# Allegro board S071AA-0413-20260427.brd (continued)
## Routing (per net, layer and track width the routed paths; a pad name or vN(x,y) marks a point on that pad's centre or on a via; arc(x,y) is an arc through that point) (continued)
N23050554: length 1.5
  TOP w0.305: LD46.1 R46.1
N23057413: length 133.1
  L11_DPS w0.203: v1(163.86,212.67) 170.21,212.67 171.89,214.34 171.89,239.49 169.98,241.4 151.11,241.4 112.36,280.15 112.36,292.73 113.16,293.53 117.26,293.53 v1(118.38,292.42) v1(120.92,292.42)
  BOTTOM w0.152: v1(163.86,212.67) 162.9,212.67 SH5.2
N23057441: length 127.8
  L11_DPS w0.203: v1(113.3,292.42) v1(115.84,292.42) 114.39,290.97 114.39,279.37 151.87,241.88 170.86,241.88 172.64,240.11 172.64,213.5 170.81,211.68 v1(163.86,211.68)
  BOTTOM w0.152: SH6.2 v1(163.86,211.68)
N23058541: length 225.3
  L11_DPS w0.203: v1(143.78,292.42) v1(141.24,292.42) 140.31,293.35 135.28,293.35 134.48,292.55 134.48,292 135.13,291.34 137.89,291.34 141.59,287.64 141.59,272.25 155.57,258.27 197.79,258.27 205.81,250.26 205.81,223.84 206.53,223.11 206.53,200.69 194.08,188.24 159.13,188.24 150.26,197.11 v1(149.14,197.11)
  BOTTOM w0.152: SH7.2 v1(149.14,197.11)
N23058569: length 217.7
  L11_DPS w0.203: v1(148.13,197.11) 157.94,187.3 194.57,187.3 207.5,200.22 207.5,223.52 206.73,224.3 206.73,250.33 198.16,258.9 156.02,258.9 142.74,272.18 142.74,288.38 v1(138.7,292.42) v1(136.16,292.42)
  BOTTOM w0.152: v1(148.13,197.11) 148.13,198.11 SH8.2
N23059275: length 153.6
  L09_DPS w0.203: v1(129.59,212.67) 129.06,212.67 120.13,221.59 120.13,242.14 113.46,248.81 79.07,248.81 66.08,261.81 66.08,290.94 63.96,293.05 42.81,293.05 v1(42.18,292.42) v1(39.64,292.42)
  BOTTOM w0.152: SH9.2 v1(129.59,212.67)
N23059303: length 158.8
  L09_DPS w0.203: v1(34.56,292.42) v1(37.1,292.42) 38.34,293.66 64.65,293.66 67.13,291.17 67.13,261.91 79.24,249.8 113.68,249.8 120.89,242.59 120.89,222.22 v1(129.59,213.51)
  BOTTOM w0.152: SH10.2 v1(129.59,213.51)
N23060072: length 110.1
  L11_DPS w0.203: v1(92.98,292.42) v1(90.44,292.42) 89.49,293.37 84.84,293.37 84.26,292.79 84.26,291.64 87.19,288.71 87.19,266.14 93.91,259.42 108.05,259.42 133.75,233.73 144.62,233.73 v1(145.14,234.25)
  BOTTOM w0.152: SH11.2 v1(145.14,234.25)
N23060100: length 99.5
  L11_DPS w0.203: v1(85.36,292.42) v1(87.9,292.42) 88.96,291.36 88.96,268.95 96.78,261.14 107.96,261.14 132.7,236.4 144.58,236.4 146.01,234.97 v1(146.01,234.25)
  BOTTOM w0.152: SH12.2 v1(146.01,234.25)
N23060930: length 79.5
  L16_DPS w0.203: v1(139.86,234.41) 139.86,267.48 143.83,271.45 146.92,271.45 157.56,282.09 157.56,290.1 160.67,293.21 165.85,293.21 v1(166.64,292.42) v1(169.18,292.42)
  BOTTOM w0.152: SH13.2 v1(139.86,234.41)
N23060958: length 73.2
  L16_DPS w0.203: v1(140.94,234.41) 140.94,248.77 140.47,249.24 140.47,266.74 143.2,269.47 147.12,269.47 158.61,280.96 158.61,289.47 v1(161.56,292.42) v1(164.1,292.42)
  BOTTOM w0.152: SH14.2 v1(140.94,234.41)
N23062789: length 93.5
  L16_DPS w0.203: v1(199.66,292.42) v1(197.12,292.42) 184.21,279.52 184.21,235.82 166.69,218.29 v1(163.47,218.29)
  BOTTOM w0.152: v1(163.47,218.29) 162.49,218.29 SH15.2
N23062817: length 90.4
  L16_DPS w0.203: v1(163.47,219.18) 164.75,219.18 182.78,237.21 182.78,280.62 v1(194.58,292.42) v1(192.04,292.42)
  BOTTOM w0.152: SH16.2 v1(163.47,219.18)

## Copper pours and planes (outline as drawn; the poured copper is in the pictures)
AGND on L13_CBIT (solid shape): outline of 130 points within 248.29,391.56 250.08,411.07
AGND on L13_CBIT (solid shape): outline of 131 points within 95.92,401.67 97.72,411.13
AGND on L13_CBIT (solid shape): outline of 132 points within 243.18,391.51 245.03,411.11
AGND on L13_CBIT (solid shape): outline of 146 points within 95.92,366.11 97.72,370.49
AGND on L13_CBIT (solid shape): outline of 146 points within 95.92,361.03 97.72,365.41
AGND on L13_CBIT (solid shape): outline of 146 points within 95.92,350.87 97.72,355.25
AGND on L13_CBIT (solid shape): outline of 146 points within 95.92,340.71 97.72,345.09
AGND on L13_CBIT (solid shape): outline of 146 points within 98.43,366.12 100.25,373.02
AGND on L13_CBIT (solid shape): outline of 146 points within 98.43,358.5 100.25,362.86
AGND on L13_CBIT (solid shape): outline of 146 points within 98.43,348.34 100.25,352.7
AGND on L13_CBIT (solid shape): outline of 146 points within 98.43,338.18 100.25,342.54
AGND on L13_CBIT (solid shape): outline of 210 points within 95.92,391.51 97.72,400.97
AGND on L13_CBIT (solid shape): outline of 210 points within 95.92,381.35 97.72,390.81
AGND on L13_CBIT (solid shape): outline of 210 points within 95.92,371.19 97.72,380.65
AGND on L13_CBIT (solid shape): outline of 210 points within 98.43,394.06 100.25,403.5
AGND on L13_CBIT (solid shape): outline of 210 points within 98.43,383.9 100.25,393.34
AGND on L13_CBIT (solid shape): outline of 210 points within 98.43,373.74 100.25,383.18
AGND on L13_CBIT (solid shape): outline of 210 points within 248.29,371.24 250.08,390.76
AGND on L13_CBIT (solid shape): outline of 210 points within 248.29,350.92 250.08,370.44
AGND on L13_CBIT (solid shape): outline of 210 points within 248.29,330.6 250.08,350.12
AGND on L13_CBIT (solid shape): outline of 210 points within 261.02,373.71 262.83,393.37
AGND on L13_CBIT (solid shape): outline of 210 points within 261.02,353.39 262.83,373.05
AGND on L13_CBIT (solid shape): outline of 210 points within 261.02,333.07 262.83,352.73
AGND on L13_CBIT (solid shape): outline of 212 points within 243.18,371.19 245.03,390.81
AGND on L13_CBIT (solid shape): outline of 212 points within 243.18,350.87 245.03,370.49
AGND on L13_CBIT (solid shape): outline of 212 points within 243.18,330.55 245.03,350.17
AGND on L13_CBIT (solid shape): outline of 212 points within 245.74,373.72 247.58,393.36
AGND on L13_CBIT (solid shape): outline of 212 points within 245.74,353.4 247.58,373.04
AGND on L13_CBIT (solid shape): outline of 212 points within 245.74,333.08 247.58,352.72
AGND on L13_CBIT (solid shape): outline of 207 points within 250.79,373.71 252.61,393.37
AGND on L13_CBIT (solid shape): outline of 207 points within 250.79,353.39 252.61,373.05
AGND on L13_CBIT (solid shape): outline of 207 points within 250.79,333.07 252.61,352.73
AGND on L13_CBIT (solid shape): outline of 208100 points within 1.27,1.27 291.37,427.99
AGND on TOP, BOTTOM, L02_DGND, L03_DIG, L04_DGND, L05_DIG, L06_DGND, L07_DIG, L08_DGND, L09_DPS, L10_DGND, L11_DPS, L12_DGND, L15_DGND, L16_DPS, L17_DGND, L18_DIG, L19_DGND, L20_DIG, L21_DGND, L22_DIG, L23_DGND, L24_DIG, L25_DGND: 1.27,1.27 1.27,427.99 61.29,427.99 72.66,422.33 84.03,427.99 208.61,427.99 219.98,422.33 231.35,427.99 291.37,427.99 291.37,1.27 157.67,1.27 157.15,1.95 156.3,2.86 155.37,3.69 154.37,4.44 153.32,5.1 152.21,5.66 151.05,6.12 149.86,6.49 148.64,6.74 147.4,6.89 146.16,6.93 144.92,6.86 143.68,6.69 142.47,6.4 141.29,6.02 140.14,5.53 139.04,4.94 138,4.26 137.02,3.49 136.11,2.64 135.28,1.71 134.95,1.27
GND12A_SCG on L08_DGND: 122.68,293.61 129.2,293.61 131,295.41 131,333.2 130.1,334.1 123.98,334.1 122.03,332.14 122.03,294.26
GND12A_SCG on L10_DGND: 190.43,206.45 193.06,209.09 193.06,242.43 184.05,251.45 157.57,251.45 133.52,275.5 133.52,288.16 128.13,293.56 123.27,293.56 121.08,291.36 121.08,291.22 120.85,290.99 116.44,290.99 115.13,289.69 115.13,279.33 152.14,242.33 171.79,242.33 172.72,241.39 172.85,241.39 173.49,240.76 173.49,213.43 171.04,210.98 150.43,210.98 149.97,210.52 147.98,210.52 147.83,210.37 147.83,208.05 149.43,206.45
GND12A_SCG on L10_DGND: 122.68,293.61 122.55,293.75 120.52,293.75 119.29,294.97 119.29,308.34 111.77,315.85 111.77,316.97 111.77,316.98 111.77,403.79 112.52,404.54 188.59,404.54 192.67,408.63 192.67,415.82 193.8,416.95 198.74,416.95 199.69,416.01 199.69,372.13 175.94,348.38 127.88,348.38 124.89,345.4 124.89,337.02 125.12,336.79 129.34,336.79 134.07,332.06 134.07,329.59 133.73,329.25 133.73,298.81 131,296.08 131,295.41 129.2,293.61
GND12A_SCG on L12_DGND: 190.43,206.45 193.06,209.09 193.06,242.43 184.05,251.45 157.57,251.45 133.52,275.5 133.52,288.16 128.13,293.56 123.27,293.56 121.08,291.36 121.08,291.22 120.85,290.99 116.44,290.99 115.13,289.69 115.13,279.33 152.14,242.33 171.79,242.33 172.72,241.39 172.85,241.39 173.49,240.76 173.49,213.43 171.04,210.98 150.43,210.98 149.41,209.96 148.94,209.96 148.88,210.02 148.88,210.43 148.79,210.52 147.98,210.52 147.83,210.37 147.83,208.05 149.43,206.45
GND12A_SCG on L12_DGND: 128.67,293.75 133.73,298.81 133.73,329.25 134.07,329.59 134.07,332.06 129.34,336.79 125.12,336.79 124.89,337.02 124.89,345.4 127.88,348.38 175.94,348.38 199.69,372.13 199.69,416.01 198.74,416.95 193.8,416.95 192.67,415.82 192.67,408.63 188.59,404.54 112.52,404.54 111.77,403.79 111.77,316.98 111.77,316.97 111.77,315.85 119.29,308.34 119.29,294.97 120.52,293.75
GND33A_ADC12 on L02_DGND, L04_DGND, L06_DGND, L08_DGND, L17_DGND, L19_DGND: 143.27,210.59 146.07,210.59 146.27,210.39 146.27,207.02 145.78,206.53 145.78,187.2 152.13,180.84 154.44,180.84 155.32,179.96 155.32,163.89 156.53,162.68 159.56,162.68 191.45,130.78 191.45,98.12 188.5,95.16 162.35,95.16 160.44,97.07 160.44,107.73 145.97,122.2 127.22,122.2 111.63,137.79 111.63,179.81 115.82,183.99 122.17,183.99 142.39,204.21 142.39,208.02 142.65,208.29 143.05,208.29 143.15,208.4 143.15,210.47
GND33A_ADC12 on L08_DGND: 145.55,293.44 151.67,293.44 152.47,294.25 152.47,330.37 138.64,344.21 126.51,344.21 125.84,343.53 125.84,339.82 126.49,339.17 134.43,339.17 138.32,335.28 138.32,300.68
GND33A_ADC12 on L10_DGND: 277.39,10.65 275.77,12.27 275.77,21.4 272.6,24.57 272.6,293 271.49,294.11 152.33,294.11 151.67,293.44 145.55,293.44 138.32,300.68 138.32,335.28 134.43,339.17 126.49,339.17 125.84,339.82 125.84,343.53 126.51,344.21 138.64,344.21 152.47,330.37 152.47,306.47 165.13,319.13 285.28,319.13 289.19,315.22 289.19,10.65
GND33A_ADC12 on L10_DGND: 146.48,213.01 147.75,213.01 148.21,212.56 148.21,211.56 148.13,211.48 147.23,211.48 146.76,211.02 146.76,210.12 146.77,210.12 144.93,208.29 144.93,206.56 147.36,204.13 147.46,204.13 147.46,196.84 158.43,185.86 195.04,185.86 208.63,199.45 208.63,249.62 198.78,259.46 156.98,259.46 143.15,273.29 143.15,290.06 145.73,292.64 213.54,292.64 233.51,272.67 233.51,183.94 220.83,171.27 146.66,171.27 137.22,180.71 137.22,199.46 142.48,204.71 142.48,208 142.65,208.17 142.92,208.17 143.14,208.39 143.13,208.39 143.13,209.77 144.31,210.95 145.59,210.95 146.36,211.72 146.36,212.9
GND33A_ADC12 on L12_DGND: 271.49,294.11 272.6,293 272.6,24.57 275.77,21.4 275.77,12.27 277.39,10.65 289.19,10.65 289.19,315.22 285.28,319.13 165.13,319.13 148.48,302.48 148.48,294.14 150.94,294.14 150.98,294.11
GND33A_ADC12 on L12_DGND: 146.48,213.01 147.75,213.01 148.21,212.56 148.21,211.56 148.13,211.48 147.23,211.48 146.76,211.02 146.76,210.12 146.77,210.12 144.93,208.29 144.93,206.56 147.36,204.13 147.46,204.13 147.46,196.84 158.43,185.86 195.04,185.86 208.63,199.45 208.63,249.62 198.78,259.46 156.98,259.46 143.15,273.29 143.15,290.06 145.73,292.64 213.54,292.64 233.51,272.67 233.51,183.94 220.83,171.27 146.66,171.27 137.22,180.71 137.22,199.46 142.34,204.58 142.34,207.95 142.65,208.26 142.65,209.29 144.31,210.95 145.59,210.95 146.36,211.72 146.36,212.9
GND33A_ADC12 on L23_DGND, L25_DGND: 26.93,384.88 26.93,379.68 28.5,378.11 54.21,378.11 54.26,378.16 56.89,378.16 60.17,374.88 60.17,261.68 66.28,255.57 103.97,255.57 108.36,251.17 108.36,139.58 113.72,134.23 152.71,134.23 155.95,137.46 155.95,166.66 153.22,169.39 120.59,169.39 115.13,174.84 115.13,255.26 115.33,255.46 107.86,262.94 69.27,262.94 65.12,267.08 65.12,379.02 58.66,385.49 27.54,385.49
GND33A_ADC32 on L02_DGND: 137.72,212.17 129.78,212.17 120.93,221.02 120.93,240.99 117.98,243.95 27.82,243.95 22.91,239.04 22.91,204.58 21.9,203.57 21.9,162.68 12.45,153.23 12.45,77.58 15.04,74.99 56.42,74.99 57.72,76.28 57.72,111.28 70.27,123.83 70.27,156.69 98.8,185.22 117.42,185.22 120.46,188.26 120.46,199.01 127.71,206.25 141.62,206.25 142.21,206.84 142.21,207.9 142.59,208.28 142.91,208.28 143.07,208.44 143.07,212.03 142.1,213.01 138.53,213.01 138.53,212.98
GND33A_ADC32 on L04_DGND: 137.72,212.17 129.78,212.17 120.93,221.02 120.93,240.99 117.98,243.95 27.82,243.95 22.91,239.04 22.91,204.58 21.9,203.57 21.9,162.68 12.45,153.23 12.45,77.58 15.04,74.99 56.42,74.99 57.72,76.28 57.72,111.28 70.27,123.83 70.27,156.69 98.8,185.22 117.42,185.22 120.46,188.26 120.46,199.01 127.71,206.25 141.62,206.25 142.21,206.84 142.21,208.05 142.47,208.31 142.93,208.31 143.06,208.45 143.06,210.37 143.04,210.37 142.36,211.04 142.38,211.06 142.38,212.66 142.02,213.03 138.55,213.03 138.55,212.99
GND33A_ADC32 on L06_DGND: 137.55,212.17 129.78,212.17 120.93,221.02 120.93,240.99 117.98,243.95 27.82,243.95 22.91,239.04 22.91,204.58 21.9,203.57 21.9,162.68 12.45,153.23 12.45,77.58 15.04,74.99 56.42,74.99 57.72,76.28 57.72,111.28 70.27,123.83 70.27,156.69 98.8,185.22 117.42,185.22 120.46,188.26 120.46,199.01 127.71,206.25 141.62,206.25 142.21,206.84 142.21,208.23 142.29,208.31 142.91,208.31 143.05,208.45 143.05,210.5 143.01,210.5 142.4,211.11 142.4,212.62 142,213.02 138.32,213.02 137.55,212.25
GND33A_ADC32 on L08_DGND: 15.04,74.99 12.45,77.58 12.45,153.23 21.9,162.68 21.9,203.57 22.91,204.58 22.91,239.04 27.82,243.95 43.73,243.95 43.73,270.18 41.24,272.68 41.24,289.31 44.52,292.59 62.5,292.59 63.87,291.22 63.87,262.3 78.94,247.23 113.39,247.23 113.39,247.17 116.61,243.95 117.98,243.95 120.93,240.99 120.93,221.02 129.78,212.17 137.72,212.17 138.56,213 139.94,213 139.95,212.99 142.31,212.99 142.72,213.4 145.79,213.4 146.21,212.99 146.21,211.86 145.68,211.33 145.68,211.31 145.43,211.06 144.02,211.06 143.73,210.77 143.73,210.5 143.07,209.84 143.07,208.48 142.89,208.3 142.36,208.3 142.36,206.83 141.46,205.93 128.07,205.93 127.69,205.55 127.69,205.54 120.46,198.31 120.46,188.26 117.42,185.22 98.8,185.22 70.27,156.69 70.27,123.83 57.72,111.28 57.72,76.28 56.42,74.99
GND33A_ADC32 on L08_DGND, L10_DGND: 52.9,294.1 54.01,295.21 54.01,315.66 51.6,318.07 33.4,318.07 28.9,322.57 28.9,333.32 28.08,334.14 15.18,334.14 14.29,333.26 14.29,307.29 18.35,303.23 37.62,303.23 43.63,297.23 43.63,294.95 44.48,294.1 44.48,294.1
GND33A_ADC32 on L10_DGND: 142.72,213.4 145.79,213.4 146.21,212.99 146.21,211.86 145.68,211.33 145.68,211.31 145.43,211.06 144.02,211.06 143.73,210.77 143.73,210.5 143.03,209.8 143.03,208.46 142.75,208.18 142.36,208.18 142.36,206.83 141.46,205.93 128.07,205.93 127.69,205.55 127.69,205.54 120.3,198.15 61.05,198.15 43.73,215.47 43.73,270.18 41.24,272.68 41.24,289.31 44.52,292.59 62.5,292.59 63.87,291.22 63.87,262.3 78.94,247.23 113.39,247.23 113.39,247.17 119.67,240.89 119.67,221.34 128.96,212.04 138.16,212.04 138.16,212.58 138.58,213 141.14,213 141.17,212.97 142.29,212.97
GND33A_ADC32 on L15_DGND: 43.47,295.57 43.47,291.37 13.76,261.66 13.76,50.67 21.41,43.02 123.84,43.02 124.04,43.22 243.55,43.22 243.56,43.23 262.94,43.23 265.5,40.67 265.5,12.94 267.8,10.64 271.76,10.64 272.46,11.34 272.46,58.55 265.59,65.42 242.54,65.42 242.41,65.29 232.14,65.29 224.24,73.19 145.94,73.19 92.72,126.4 92.72,153.05 58.04,187.73 58.04,292.43 52.73,297.74 45.64,297.74
GND33A_ADC32 on L17_DGND: 267.8,10.64 265.5,12.94 265.5,40.67 262.94,43.23 243.56,43.23 243.55,43.22 124.04,43.22 123.84,43.02 21.41,43.02 13.76,50.67 13.76,76.26 12.45,77.58 12.45,153.23 13.76,154.55 13.76,261.66 43.47,291.37 43.47,295.57 45.64,297.74 52.73,297.74 58.04,292.43 58.04,243.95 117.98,243.95 120.93,240.99 120.93,221.02 129.78,212.17 137.04,212.17 137.85,212.97 142.14,212.97 142.36,212.76 142.36,211.04 142.29,210.98 142.73,210.54 143.03,210.54 143.03,208.4 142.9,208.27 142.21,208.27 142.21,206.84 141.62,206.25 127.71,206.25 120.46,199.01 120.46,188.26 117.42,185.22 98.8,185.22 79.67,166.1 92.72,153.05 92.72,126.4 145.94,73.19 224.24,73.19 232.14,65.29 242.41,65.29 242.54,65.42 265.59,65.42 272.46,58.55 272.46,11.34 271.76,10.64
GND33A_ADC32 on L19_DGND: 137.51,212.17 129.78,212.17 120.93,221.02 120.93,240.99 117.98,243.95 27.82,243.95 22.91,239.04 22.91,204.58 21.9,203.57 21.9,162.68 12.45,153.23 12.45,77.58 15.04,74.99 56.42,74.99 57.72,76.28 57.72,111.28 70.27,123.83 70.27,156.69 98.8,185.22 117.42,185.22 120.46,188.26 120.46,199.01 127.71,206.25 141.62,206.25 142.21,206.84 142.21,208.28 143,208.28 143.04,208.32 143.04,210.6 143,210.65 142.57,210.65 142.35,210.87 142.35,212.75 142.04,213.05 138.37,213.05 137.51,212.19
GND33A_ADC32 on L21_DGND: 138.13,212.17 129.78,212.17 120.93,221.02 120.93,240.99 117.98,243.95 27.82,243.95 22.91,239.04 22.91,204.58 21.9,203.57 21.9,162.68 12.45,153.23 12.45,77.58 15.04,74.99 56.42,74.99 57.72,76.28 57.72,111.28 70.27,123.83 70.27,156.69 98.8,185.22 117.42,185.22 120.46,188.26 120.46,199.01 127.71,206.25 141.62,206.25 142.21,206.84 142.21,208.23 142.26,208.28 142.9,208.28 143.04,208.42 143.04,210.42 142.9,210.56 142.38,210.56 142.28,210.65 142.28,212.75 142.06,212.97 138.44,212.97 138.35,212.88 138.35,212.38
GND33A_ADC32 on L23_DGND, L25_DGND: 11.79,384.78 21.44,384.78 21.91,384.3 21.91,377.31 15.95,371.34 15.95,257.54 28.23,245.26 103.24,245.26 103.44,245.46 105.26,243.65 105.26,187.63 102.23,184.59 27.98,184.59 22.72,189.85 22.72,246.32 11.76,257.28 11.76,384.74
GNDA_REG on L02_DGND, L04_DGND: 148.01,214.63 148.6,214.63 148.79,214.44 148.79,212.84 149.02,212.6 155.92,212.6 156.57,213.25 159.14,213.25 159.4,213.51 169.21,213.51 175.08,219.38 196.47,219.38 237.67,178.17 237.67,95.79 237.06,95.17 234.82,95.17 233.71,96.28 233.71,176.64 194.61,215.75 178.12,215.75 177.09,214.72 177.09,212.33 175.84,211.08 165,211.08 164.73,210.81 156.85,210.81 155.82,211.84 155.82,211.84 148.46,211.84 147.88,212.42 147.88,214.5
GNDA_REG on L08_DGND: 94.9,293.41 99.41,293.41 102.69,296.69 102.69,332.53 101.3,333.92 90.91,333.92 88.87,331.88 88.87,300.08 94.5,294.45 94.5,293.81
GNDA_REG on L10_DGND: 94.9,293.41 94.67,293.64 94.48,293.64 92.14,295.97 92.14,296.81 88.87,300.08 88.87,331.88 90.91,333.92 92.14,333.92 92.14,410.91 98.61,417.39 188.15,417.39 189.38,416.16 189.38,409.4 188.38,408.39 109.95,408.39 105.57,404.01 105.57,297.88 101.32,293.64 99.63,293.64 99.41,293.41
GNDA_REG on L10_DGND, L12_DGND: 148.04,213.11 154.05,213.11 157.99,217.05 157.99,231.56 120.22,269.32 120.22,270.3 119.32,271.2 116.81,271.2 111.65,276.37 111.65,281.51 100.01,293.15 94.9,293.15 90.67,288.92 90.67,268.85 97.68,261.83 108.87,261.83 133.49,237.22 144.73,237.22 146.78,235.16 146.78,225.18 148.04,223.92
GNDA_REG on L12_DGND: 94.48,293.64 101.32,293.64 105.57,297.88 105.57,404.01 109.95,408.39 188.38,408.39 189.38,409.4 189.38,416.16 188.15,417.39 98.61,417.39 92.14,410.91 92.14,295.97
(no net) on L13_CBIT: 1.27,1.27 1.27,427.99 61.29,427.99 72.66,422.33 84.03,427.99 208.61,427.99 219.98,422.33 231.35,427.99 291.37,427.99 291.37,1.27 157.67,1.27 157.15,1.95 156.3,2.86 155.37,3.69 154.37,4.44 153.32,5.1 152.21,5.66 151.05,6.12 149.86,6.49 148.64,6.74 147.4,6.89 146.16,6.93 144.92,6.86 143.68,6.69 142.47,6.4 141.29,6.02 140.14,5.53 139.04,4.94 138,4.26 137.02,3.49 136.11,2.64 135.28,1.71 134.95,1.27
GPDPS1_1F on L16_DPS: 204.99,295.77 204.99,294.38 205.27,294.1 205.27,294.08 209.32,294.08 209.63,293.77 209.63,293.75 211.89,291.5 211.89,221.2 201.3,210.61 199.68,210.61 199.53,210.76 166.93,210.76 164.48,208.31 163.43,208.31 163.4,208.33 162.55,208.33 157.55,203.34 157.55,185.9 230.1,113.34 230.1,78.87 238.02,70.95 272.05,70.95 276.56,66.44 276.56,13.44 272.2,9.08 248.75,9.08 246.54,11.28 246.54,18.55 244.76,20.33 241.08,20.33 240.39,19.64 240.39,5.81 242.11,4.09 283.5,4.09 285.86,6.44 285.86,87.22 174.41,198.67 174.41,205.48 174.8,205.86 217.64,205.86 222.06,210.29 222.06,295.06 221,296.13 205.35,296.13
GPDPS1_2F on L16_DPS: 5.54,2.57 225.32,2.57 231.44,8.69 231.44,19.41 233.35,21.32 233.35,21.46 234.19,22.3 249.52,22.3 250.65,21.17 250.65,12.56 258.58,12.56 259.63,13.61 259.63,30.59 256.6,33.62 14.16,33.62 9.75,38.03 9.75,181.64 10.03,181.93 10.03,268.75 10.21,268.75 31.97,290.51 32.07,290.51 32.27,290.71 32.27,296.52 37.23,301.48 163.3,301.48 167.73,297.05 167.73,295.3 168.06,294.97 170.34,294.97 171.2,294.11 172.74,294.11 172.99,294.35 172.99,311.07 149.66,334.4 12.66,334.4 1.75,323.49 1.3,323.04 1.3,6.81
GPDPS1_3F on L16_DPS: 43.47,295.57 43.47,291.37 13.76,261.66 13.76,50.67 21.41,43.02 123.84,43.02 124.04,43.22 243.55,43.22 243.56,43.23 262.94,43.23 265.5,40.67 265.5,12.94 267.8,10.64 271.76,10.64 272.46,11.34 272.46,58.55 265.59,65.42 242.54,65.42 242.41,65.29 232.14,65.29 224.24,73.19 145.94,73.19 92.72,126.4 92.72,153.05 58.04,187.73 58.04,292.43 52.73,297.74 45.64,297.74
GPDPS1_4F on L11_DPS: 271.49,294.11 272.6,293 272.6,24.57 275.77,21.4 275.77,12.27 277.39,10.65 289.19,10.65 289.19,315.22 285.28,319.13 165.13,319.13 148.48,302.48 148.48,294.14 150.94,294.14 150.98,294.11
GPDPS2_1F on L11_DPS: 128.67,293.75 133.73,298.81 133.73,329.25 134.07,329.59 134.07,332.06 129.34,336.79 125.12,336.79 124.89,337.02 124.89,345.4 127.88,348.38 175.94,348.38 199.69,372.13 199.69,416.01 198.74,416.95 193.8,416.95 192.67,415.82 192.67,408.63 188.59,404.54 112.52,404.54 111.77,403.79 111.77,316.98 111.77,316.97 111.77,315.85 119.29,308.34 119.29,294.97 120.52,293.75
GPDPS2_2F on L11_DPS: 94.48,293.64 101.32,293.64 105.57,297.88 105.57,404.01 109.95,408.39 188.38,408.39 189.38,409.4 189.38,416.16 188.15,417.39 98.61,417.39 92.14,410.91 92.14,295.97
GPDPS2_3F on L16_DPS: 236.93,294.22 236.93,386.74 216.56,407.12 176.12,407.12 174.09,409.15 174.09,416.86 173.36,417.59 167.73,417.59 166.63,416.5 166.63,390.79 166.65,390.79 167.16,390.28 202.5,390.28 213.41,379.37 213.41,315.18 234.37,294.22
S1_CSDPS1-1F on L16_DPS: 269.25,294.06 281.4,306.21 281.4,410.94 273.41,418.94 216.26,418.94 216.16,418.84 212.93,418.84 204.84,426.93 204.23,426.93 204.16,426.86 203.03,426.86 203.01,426.88 88.77,426.88 81.05,419.16 64.86,419.16 58.8,425.22 5.19,425.22 2.78,422.82 2.78,344.15 7.44,339.48 21.58,339.48 21.64,339.43 21.65,339.44 31.56,339.44 37.23,345.1 37.23,388.7 52.26,403.73 148.27,403.73 150.07,405.53 150.07,406.04 164.8,420.77 174.02,420.77 177.73,417.06 178.23,417.06 178.23,409.39 178.94,408.68 213.85,408.68 214.04,408.49 239.38,408.49 251.8,396.07 251.8,309.4 240.36,297.96 238.36,295.96 238.37,295.95 238.37,294.29 238.6,294.06
S1_CSDPS2-1F on L09_DPS: 122.68,293.61 129.2,293.61 131,295.41 131,333.2 130.1,334.1 123.98,334.1 122.03,332.14 122.03,294.26
S1_CSDPS3-1F on L09_DPS: 145.55,293.44 151.67,293.44 152.47,294.25 152.47,330.37 138.64,344.21 126.51,344.21 125.84,343.53 125.84,339.82 126.49,339.17 134.43,339.17 138.32,335.28 138.32,300.68
S1_CSDPS4-1F on L09_DPS: 52.9,294.1 54.01,295.21 54.01,315.66 51.6,318.07 33.4,318.07 28.9,322.57 28.9,333.32 28.08,334.14 15.18,334.14 14.29,333.26 14.29,307.29 18.35,303.23 37.62,303.23 43.63,297.23 43.63,294.95 44.48,294.1 44.48,294.1
S1_CSDPS5-1F on L09_DPS: 94.9,293.41 99.41,293.41 102.69,296.69 102.69,332.53 101.3,333.92 90.91,333.92 88.87,331.88 88.87,300.08 94.5,294.45 94.5,293.81
S1_CSDPS6-1F on L16_DPS: 180.95,294.05 181.64,294.74 181.64,328.1 140.84,368.9 93.15,368.9 88.54,364.29 88.54,341.9 91.05,339.39 150.69,339.39 174.76,315.32 174.76,294.21 174.92,294.05
S1_CSDPS7-1F on L16_DPS: 176.09,376.61 155.57,397.12 57.16,397.12 44.23,384.19 44.23,344.71 49.74,339.2 56.86,339.2 59.82,342.15 59.82,370.23 67.64,378.05 143.88,378.05 164.18,357.76 183.77,357.76 186.85,354.68 186.85,307.68 186.86,307.66 186.86,307.23 199.14,294.95 200.91,294.95 200.91,294.44 201.3,294.05 203.46,294.05 203.66,294.25 203.66,299.28 204.11,299.73 204.11,372.26 199.6,376.77 191.99,376.77 191.82,376.61
S1_DPS11 on L16_DPS: 148.94,212.31 149.87,213.24 149.87,213.92 150.2,214.25 200.05,214.25 207.28,221.47 207.28,275.49 209.59,277.79 209.59,289.94 206.98,292.54 200.94,292.54 200.13,291.74 198.47,291.74 185.63,278.9 185.63,236.35 167.19,217.92 167.19,217.88 156.2,217.88 155.27,216.95 144.22,216.95 144.22,216.94 144.09,216.81 144.09,212.54 144.34,212.28 144.37,212.31
S1_DPS12 on L16_DPS: 150.93,213.85 156.31,213.85 156.96,213.19 156.96,210.6 151.88,210.6 150.98,209.7 146.73,209.7 145.78,210.65 143.42,210.65 143.16,210.91 143.16,212.09 142.17,213.07 141.82,213.07 141.59,213.3 141.59,218.7 142.03,218.7 142.24,218.91 142.24,222.64 141.59,223.28 141.59,262.83 159.37,280.6 159.37,287.37 163.22,291.23 169.99,291.23 171.17,292.4 171.37,292.4 171.54,292.57 178.21,292.57 179.26,291.51 179.26,255.84 151.72,228.29 151.72,219.02 151,218.31 145.24,218.31 145.24,218.27 143.91,216.94 143.91,212.52 144.3,212.14 149.22,212.14
S1_DPS13 on L09_DPS: 142.72,213.4 145.79,213.4 146.21,212.99 146.21,211.86 145.68,211.33 145.68,211.31 145.43,211.06 144.02,211.06 143.73,210.77 143.73,210.5 142.33,209.09 142.33,209.01 142.36,208.97 142.36,206.83 141.46,205.93 128.07,205.93 127.69,205.55 127.69,205.54 120.3,198.15 61.05,198.15 43.73,215.47 43.73,270.18 41.24,272.68 41.24,289.31 44.52,292.59 62.5,292.59 63.87,291.22 63.87,262.3 78.94,247.23 113.39,247.23 113.39,247.17 119.67,240.89 119.67,221.34 128.96,212.04 139.93,212.04 140.55,211.42 141.62,211.42 141.81,211.62 141.81,212.49
S1_DPS14 on L11_DPS: 146.48,213.01 147.75,213.01 148.21,212.56 148.21,211.56 148.13,211.48 147.23,211.48 146.76,211.02 146.76,210.12 146.77,210.12 144.93,208.29 144.93,206.56 147.36,204.13 147.46,204.13 147.46,196.84 158.43,185.86 195.04,185.86 208.63,199.45 208.63,249.62 198.78,259.46 156.98,259.46 143.15,273.29 143.15,290.06 145.73,292.64 213.54,292.64 233.51,272.67 233.51,183.94 220.83,171.27 146.66,171.27 137.22,180.71 137.22,199.46 142.65,204.89 142.65,209.29 144.31,210.95 145.59,210.95 146.36,211.72 146.36,212.9
S1_DPS21 on L11_DPS: 190.43,206.45 193.06,209.09 193.06,242.43 184.05,251.45 157.57,251.45 133.52,275.5 133.52,288.16 128.13,293.56 123.27,293.56 121.08,291.36 121.08,291.22 120.85,290.99 116.44,290.99 115.13,289.69 115.13,279.33 152.14,242.33 171.79,242.33 172.72,241.39 172.85,241.39 173.49,240.76 173.49,213.43 171.04,210.98 150.43,210.98 149.41,209.96 148.94,209.96 148.88,210.02 148.88,210.43 148.79,210.52 147.98,210.52 147.83,210.37 147.83,208.05 149.43,206.45
S1_DPS22 on L11_DPS: 148.04,213.11 154.05,213.11 157.99,217.05 157.99,231.56 120.22,269.32 120.22,270.3 119.32,271.2 116.81,271.2 111.65,276.37 111.65,281.51 100.01,293.15 94.9,293.15 90.67,288.92 90.67,268.85 97.68,261.83 108.87,261.83 133.49,237.22 144.73,237.22 146.78,235.16 146.78,225.18 148.04,223.92
S1_DPS23 on L16_DPS: 175.16,204.23 175.16,199.62 203.61,171.17 279.57,171.17 289.6,181.19 289.6,285.12 282.1,292.62 235.18,292.62 232.16,289.6 232.16,278.09 233.99,276.26 233.99,207.82 229.28,203.12 184.25,203.12 182.62,201.48 178.52,201.48 178.52,202.52 178.53,202.54 178.56,202.51 179.28,202.51 179.61,202.84 179.61,204.19 179.06,204.73 175.66,204.73
UDBGND on L14_5V: outline of 104 points within 10.98,13.1 279.4,416.78
UT1_UP5V on L14_5V: 1.27,1.27 1.27,427.99 61.29,427.99 72.66,422.33 84.03,427.99 208.61,427.99 219.98,422.33 231.35,427.99 291.37,427.99 291.37,1.27 157.67,1.27 157.15,1.95 156.3,2.86 155.37,3.69 154.37,4.44 153.32,5.1 152.21,5.66 151.05,6.12 149.86,6.49 148.64,6.74 147.4,6.89 146.16,6.93 144.92,6.86 143.68,6.69 142.47,6.4 141.29,6.02 140.14,5.53 139.04,4.94 138,4.26 137.02,3.49 136.11,2.64 135.28,1.71 134.95,1.27

Small or netless copper shapes (teardrops, artwork), in the pictures only: 66 on L13_CBIT

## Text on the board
User.Comments: CR_11_2 | CR_UNNAMED_8 | CR_UNNAMED_1 | CR_11_6 | CR_D_4 | CR_D_34 | CR_11_14 | CR_SS_3 | CR_SS_4 | CR_SS_1 | CR_SS_2 | CR_RTY_6 | CR_RTY_5 | CR_11_1 | CR_11_3 | CR_RTY_4 | CR_RTY_3 | CR_RTY_2 | CR_RTY_1 | CR_WERT_2
